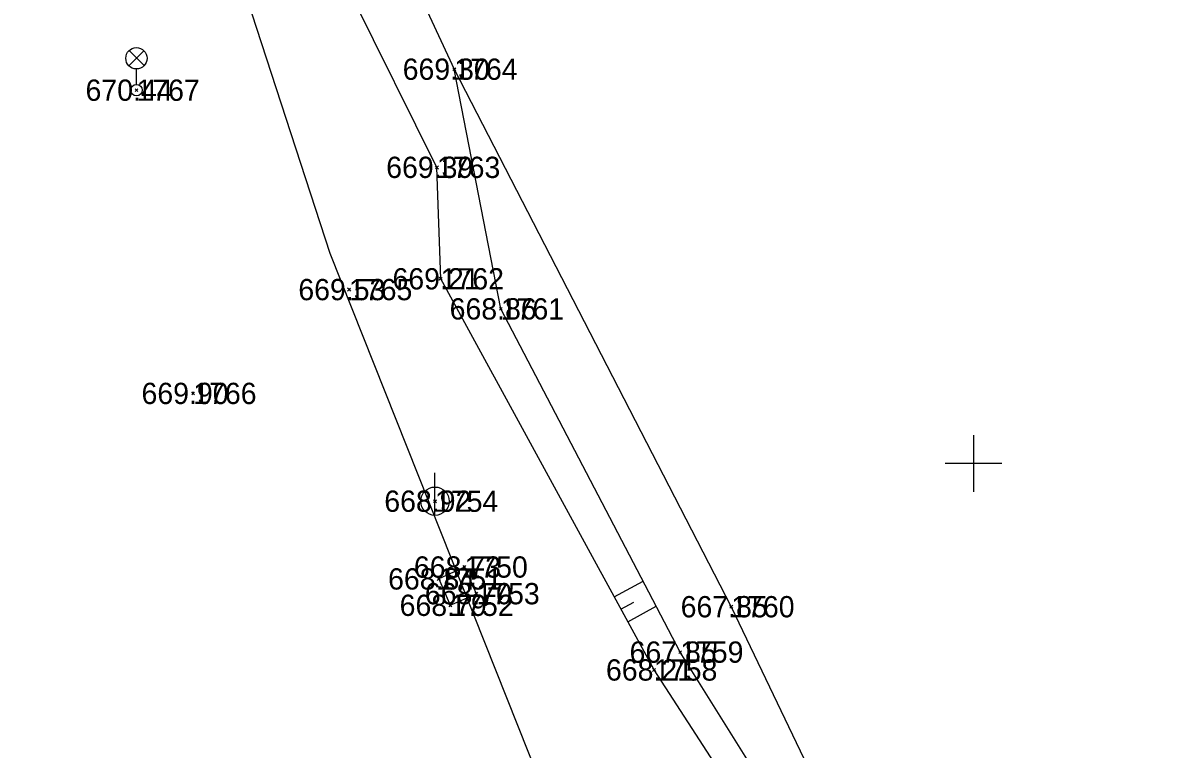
# Model space of a CAD drawing. Extents: x -844765 to -843273, y -997542 to -995529.
# Drawn here: x -844333.5 to -844293.15, y -996510.07 to -996484.47 of the extents above; entities that cross this region are included whole.
import ezdxf

# ---------------------------------------------------------------- set-up
doc = ezdxf.new("R2010")
doc.units = 0
for name, color, linetype in [('Betonový strop', 7, 'Continuous'), ('Doplněk polohopisu', 7, 'Continuous'), ('Groma', 7, 'Continuous'), ('Osa', 7, 'Continuous'), ('Přítoky', 7, 'Continuous'), ('Rámeček', 7, 'Continuous'), ('Sítě podzemní nerozlišené', 7, 'Continuous'), ('Číslo bodu', 7, 'Continuous'), ('Řezy', 7, 'Continuous')]:
    doc.layers.add(name, color=color, linetype=linetype)

msp = doc.modelspace()

# ---------------------------------------------------------------- linework, layer by layer
at = {"layer": 'Betonový strop'}
msp.add_line((-844317.52, -996504.59), (-844317.94, -996503.65), dxfattribs=at)
for points in [[(-844404.93, -996283.34), (-844395.11, -996309.68), (-844387.94, -996327.01), (-844379.85, -996344.2), (-844371.07, -996360.2), (-844364.36, -996372.36), (-844358.52, -996383.56), (-844354.38, -996391.33), (-844352.44, -996396.02), (-844349.46, -996404.19), (-844343.93, -996420.42), (-844339.33, -996436.37), (-844332.8, -996453.78), (-844328.44, -996463.53), (-844323.26, -996475.43), (-844318.3, -996486.1), (-844308.54, -996505.05), (-844303.82, -996514.91)], [(-844317.94, -996503.65), (-844318.85, -996504.07), (-844318.44, -996505), (-844317.52, -996504.59)]]:
    msp.add_lwpolyline(points, dxfattribs=at)
at = {"layer": 'Doplněk polohopisu'}
msp.add_line((-844318.98, -996501.83), (-844318.98, -996500.33), dxfattribs=at)
msp.add_circle((-844318.98, -996501.33), 0.5, dxfattribs=at)
at = {"layer": 'Groma'}
for p, q in [((-844329.764, -996485.978), (-844329.236, -996485.45)), ((-844329.228, -996485.975), (-844329.756, -996485.446)), ((-844329.5, -996486.64), (-844329.5, -996486.09))]:
    msp.add_line(p, q, dxfattribs=at)
for centre, radius in [((-844329.5, -996485.715), 0.375), ((-844329.5, -996486.84), 0.2)]:
    msp.add_circle(centre, radius, dxfattribs=at)
at = {"layer": 'Osa'}
for p, q in [((-844318.91, -996489.56), (-844325.1, -996477.1)), ((-844316.66, -996494.55), (-844318.3, -996486.1)), ((-844318.78, -996493.49), (-844318.91, -996489.56)), ((-844311.26, -996507.28), (-844318.78, -996493.49)), ((-844310.34, -996506.65), (-844316.66, -996494.55)), ((-844306.17, -996513.31), (-844310.34, -996506.65)), ((-844307.19, -996513.53), (-844311.26, -996507.28))]:
    msp.add_line(p, q, dxfattribs=at)
msp.add_lwpolyline([(-844256.985, -996614.3), (-844264.955, -996604.805), (-844272.513, -996594.138), (-844280.435, -996583.425), (-844282.85, -996581.055), (-844288.34, -996572.812), (-844293.83, -996564.57), (-844300.425, -996547.97), (-844303.975, -996538.71), (-844307.525, -996529.45), (-844315.28, -996511.19), (-844322.67, -996492.595), (-844328.875, -996473.55)], dxfattribs=at)
at = {"layer": 'Přítoky'}
for p, q in [((-844312.667, -996504.7), (-844311.649, -996504.144)), ((-844312.428, -996505.139), (-844311.977, -996504.893)), ((-844312.188, -996505.578), (-844311.186, -996505.031))]:
    msp.add_line(p, q, dxfattribs=at)
at = {"layer": 'Rámeček'}
for p, q in [((-844300, -996499), (-844300, -996501)), ((-844299, -996500), (-844301, -996500))]:
    msp.add_line(p, q, dxfattribs=at)
at = {"layer": 'Sítě podzemní nerozlišené'}
for p, q in [((-844318.3, -996486.1), (-844318.35, -996486.05)), ((-844318.3, -996486.1), (-844318.25, -996486.05)), ((-844318.3, -996486.1), (-844318.35, -996486.15)), ((-844318.3, -996486.1), (-844318.25, -996486.15)), ((-844329.5, -996486.84), (-844329.55, -996486.79)), ((-844329.5, -996486.84), (-844329.55, -996486.89)), ((-844329.5, -996486.84), (-844329.45, -996486.79)), ((-844329.5, -996486.84), (-844329.45, -996486.89)), ((-844318.91, -996489.56), (-844318.96, -996489.51)), ((-844318.91, -996489.56), (-844318.96, -996489.61)), ((-844318.91, -996489.56), (-844318.86, -996489.51)), ((-844318.91, -996489.56), (-844318.86, -996489.61)), ((-844318.78, -996493.49), (-844318.83, -996493.44)), ((-844318.78, -996493.49), (-844318.83, -996493.54)), ((-844318.78, -996493.49), (-844318.73, -996493.44)), ((-844318.78, -996493.49), (-844318.73, -996493.54)), ((-844322.01, -996493.87), (-844322.06, -996493.82)), ((-844322.01, -996493.87), (-844322.06, -996493.92)), ((-844322.01, -996493.87), (-844321.96, -996493.82)), ((-844322.01, -996493.87), (-844321.96, -996493.92)), ((-844316.66, -996494.55), (-844316.71, -996494.5)), ((-844316.66, -996494.55), (-844316.61, -996494.5)), ((-844316.66, -996494.55), (-844316.71, -996494.6)), ((-844316.66, -996494.55), (-844316.61, -996494.6)), ((-844327.5, -996497.53), (-844327.55, -996497.48)), ((-844327.5, -996497.53), (-844327.55, -996497.58)), ((-844327.5, -996497.53), (-844327.45, -996497.48)), ((-844327.5, -996497.53), (-844327.45, -996497.58)), ((-844318.98, -996501.33), (-844319.03, -996501.28)), ((-844318.98, -996501.33), (-844319.03, -996501.38)), ((-844318.98, -996501.33), (-844318.93, -996501.28)), ((-844318.98, -996501.33), (-844318.93, -996501.38)), ((-844317.94, -996503.65), (-844317.99, -996503.6)), ((-844317.94, -996503.65), (-844317.99, -996503.7)), ((-844317.94, -996503.65), (-844317.89, -996503.6)), ((-844317.94, -996503.65), (-844317.89, -996503.7)), ((-844318.85, -996504.07), (-844318.9, -996504.02)), ((-844318.85, -996504.07), (-844318.9, -996504.12)), ((-844318.85, -996504.07), (-844318.8, -996504.02)), ((-844318.85, -996504.07), (-844318.8, -996504.12)), ((-844317.52, -996504.59), (-844317.57, -996504.54)), ((-844317.52, -996504.59), (-844317.57, -996504.64)), ((-844317.52, -996504.59), (-844317.47, -996504.54)), ((-844317.52, -996504.59), (-844317.47, -996504.64)), ((-844318.44, -996505), (-844318.49, -996504.95)), ((-844318.44, -996505), (-844318.49, -996505.05)), ((-844318.44, -996505), (-844318.39, -996504.95)), ((-844318.44, -996505), (-844318.39, -996505.05)), ((-844308.54, -996505.05), (-844308.59, -996505)), ((-844308.54, -996505.05), (-844308.49, -996505)), ((-844308.54, -996505.05), (-844308.59, -996505.1)), ((-844308.54, -996505.05), (-844308.49, -996505.1)), ((-844310.34, -996506.65), (-844310.39, -996506.6)), ((-844310.34, -996506.65), (-844310.39, -996506.7)), ((-844310.34, -996506.65), (-844310.29, -996506.6)), ((-844310.34, -996506.65), (-844310.29, -996506.7)), ((-844311.26, -996507.28), (-844311.31, -996507.23)), ((-844311.26, -996507.28), (-844311.31, -996507.33)), ((-844311.26, -996507.28), (-844311.21, -996507.23)), ((-844311.26, -996507.28), (-844311.21, -996507.33))]:
    msp.add_line(p, q, dxfattribs=at)

# ---------------------------------------------------------------- texts
at = {"layer": 'Číslo bodu'}
for s, p in [('1764', (-844318.3, -996486.475)), ('1767', (-844329.5, -996487.215)), ('1763', (-844318.91, -996489.935)), ('1762', (-844318.78, -996493.865)), ('1765', (-844322.01, -996494.245)), ('1761', (-844316.66, -996494.925)), ('1766', (-844327.5, -996497.905)), ('1754', (-844318.98, -996501.705)), ('1750', (-844317.94, -996504.025)), ('1751', (-844318.85, -996504.445)), ('1753', (-844317.52, -996504.965)), ('1752', (-844318.44, -996505.375)), ('1760', (-844308.54, -996505.425)), ('1759', (-844310.34, -996507.025)), ('1758', (-844311.26, -996507.655))]:
    msp.add_text(s, height=0.75, dxfattribs=at).set_placement(p)
at = {"layer": 'Řezy'}
for s, p in [('669.30', (-844320.119, -996486.475)), ('670.44', (-844331.295, -996487.215)), ('669.39', (-844320.699, -996489.935)), ('669.21', (-844320.478, -996493.865)), ('669.53', (-844323.796, -996494.245)), ('668.86', (-844318.464, -996494.925)), ('669.90', (-844329.322, -996497.905)), ('668.92', (-844320.766, -996501.705)), ('668.73', (-844319.723, -996504.025)), ('668.84', (-844320.633, -996504.445)), ('668.70', (-844319.336, -996504.965)), ('668.79', (-844320.226, -996505.375)), ('667.85', (-844310.323, -996505.425)), ('667.85', (-844312.123, -996507.025)), ('668.21', (-844312.955, -996507.655))]:
    msp.add_text(s, height=0.75, dxfattribs=at).set_placement(p)

doc.saveas('drawing.dxf')
